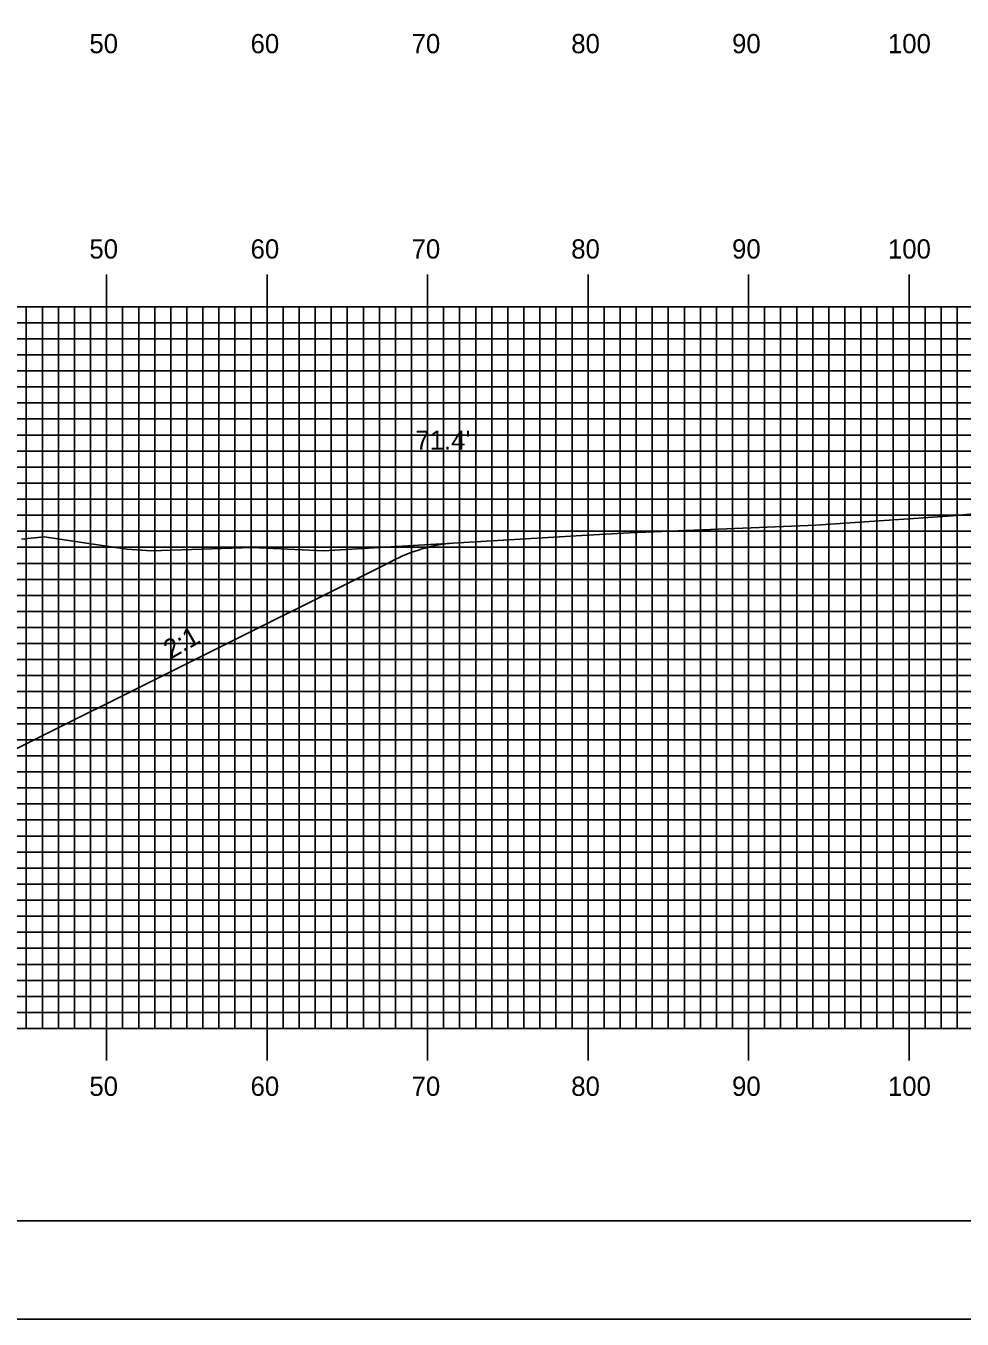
# Model space of a CAD drawing. Extents: x 1794453 to 1794796, y 442591 to 442811.
# Drawn here: x 1794663.3 to 1794721.6, y 442590.5 to 442671.2 of the extents above; entities that cross this region are included whole.
import ezdxf

# ---------------------------------------------------------------- set-up
doc = ezdxf.new("R2010")
doc.units = 0
for name, color, linetype in [('ANNOTATION', 7, 'Continuous'), ('BORDER', 7, 'Continuous'), ('D_Roadway_Centerline', 7, 'Continuous'), ('D_Roadway_SlopeLines', 7, 'Continuous'), ('D_Text_Standard', 7, 'Continuous'), ('H_V ANNOTATION', 7, 'Continuous'), ('MAJOR', 7, 'Continuous'), ('MINOR', 7, 'Continuous'), ('PLOT BOUNDARY', 7, 'Continuous'), ('S_Roadway_Centerline', 7, 'Continuous')]:
    doc.layers.add(name, color=color, linetype=linetype)

msp = doc.modelspace()

# ---------------------------------------------------------------- linework, layer by layer
at = {"layer": 'BORDER'}
msp.add_lwpolyline([(1794468.74, 442596.665), (1794788.74, 442596.665), (1794788.74, 442806.665), (1794468.74, 442806.665)], close=True, dxfattribs=at)
at = {"layer": 'D_Roadway_Centerline'}
msp.add_arc((1794690.818, 442628.973), 10, 96.45569, 116.56505, dxfattribs=at)
at = {"layer": 'D_Roadway_SlopeLines'}
for p, q in [((1794661.442, 442625.465), (1794685.8, 442637.644)), ((1794685.8, 442637.644), (1794686.346, 442637.917))]:
    msp.add_line(p, q, dxfattribs=at)
at = {"layer": 'MAJOR'}
for p, q in [((1794668.34, 442655.669), (1794668.34, 442653.665)), ((1794678.34, 442655.669), (1794678.34, 442653.665)), ((1794688.34, 442655.669), (1794688.34, 442653.665)), ((1794698.34, 442655.669), (1794698.34, 442653.665)), ((1794708.34, 442655.669), (1794708.34, 442653.665)), ((1794718.34, 442655.669), (1794718.34, 442653.665)), ((1794478.34, 442653.665), (1794758.34, 442653.665)), ((1794478.34, 442653.665), (1794758.34, 442653.665)), ((1794668.34, 442608.665), (1794668.34, 442653.665)), ((1794678.34, 442608.665), (1794678.34, 442653.665)), ((1794688.34, 442608.665), (1794688.34, 442653.665)), ((1794698.34, 442608.665), (1794698.34, 442653.665)), ((1794708.34, 442608.665), (1794708.34, 442653.665)), ((1794718.34, 442608.665), (1794718.34, 442653.665)), ((1794478.34, 442648.665), (1794758.34, 442648.665)), ((1794478.34, 442643.665), (1794758.34, 442643.665)), ((1794478.34, 442638.665), (1794758.34, 442638.665)), ((1794478.34, 442633.665), (1794758.34, 442633.665)), ((1794478.34, 442628.665), (1794758.34, 442628.665)), ((1794478.34, 442623.665), (1794758.34, 442623.665)), ((1794478.34, 442618.665), (1794758.34, 442618.665)), ((1794478.34, 442613.665), (1794758.34, 442613.665)), ((1794478.34, 442608.665), (1794758.34, 442608.665)), ((1794478.34, 442608.665), (1794758.34, 442608.665)), ((1794668.34, 442606.661), (1794668.34, 442608.665)), ((1794678.34, 442606.661), (1794678.34, 442608.665)), ((1794688.34, 442606.661), (1794688.34, 442608.665)), ((1794698.34, 442606.661), (1794698.34, 442608.665)), ((1794708.34, 442606.661), (1794708.34, 442608.665)), ((1794718.34, 442606.661), (1794718.34, 442608.665))]:
    msp.add_line(p, q, dxfattribs=at)
at = {"layer": 'MINOR'}
for p, q in [((1794663.34, 442608.665), (1794663.34, 442653.665)), ((1794664.34, 442608.665), (1794664.34, 442653.665)), ((1794665.34, 442608.665), (1794665.34, 442653.665)), ((1794666.34, 442608.665), (1794666.34, 442653.665)), ((1794667.34, 442608.665), (1794667.34, 442653.665)), ((1794669.34, 442608.665), (1794669.34, 442653.665)), ((1794670.34, 442608.665), (1794670.34, 442653.665)), ((1794671.34, 442608.665), (1794671.34, 442653.665)), ((1794672.34, 442608.665), (1794672.34, 442653.665)), ((1794673.34, 442608.665), (1794673.34, 442653.665)), ((1794674.34, 442608.665), (1794674.34, 442653.665)), ((1794675.34, 442608.665), (1794675.34, 442653.665)), ((1794676.34, 442608.665), (1794676.34, 442653.665)), ((1794677.34, 442608.665), (1794677.34, 442653.665)), ((1794679.34, 442608.665), (1794679.34, 442653.665)), ((1794680.34, 442608.665), (1794680.34, 442653.665)), ((1794681.34, 442608.665), (1794681.34, 442653.665)), ((1794682.34, 442608.665), (1794682.34, 442653.665)), ((1794683.34, 442608.665), (1794683.34, 442653.665)), ((1794684.34, 442608.665), (1794684.34, 442653.665)), ((1794685.34, 442608.665), (1794685.34, 442653.665)), ((1794686.34, 442608.665), (1794686.34, 442653.665)), ((1794687.34, 442608.665), (1794687.34, 442653.665)), ((1794689.34, 442608.665), (1794689.34, 442653.665)), ((1794690.34, 442608.665), (1794690.34, 442653.665)), ((1794691.34, 442608.665), (1794691.34, 442653.665)), ((1794692.34, 442608.665), (1794692.34, 442653.665)), ((1794693.34, 442608.665), (1794693.34, 442653.665)), ((1794694.34, 442608.665), (1794694.34, 442653.665)), ((1794695.34, 442608.665), (1794695.34, 442653.665)), ((1794696.34, 442608.665), (1794696.34, 442653.665)), ((1794697.34, 442608.665), (1794697.34, 442653.665)), ((1794699.34, 442608.665), (1794699.34, 442653.665)), ((1794700.34, 442608.665), (1794700.34, 442653.665)), ((1794701.34, 442608.665), (1794701.34, 442653.665)), ((1794702.34, 442608.665), (1794702.34, 442653.665)), ((1794703.34, 442608.665), (1794703.34, 442653.665)), ((1794704.34, 442608.665), (1794704.34, 442653.665)), ((1794705.34, 442608.665), (1794705.34, 442653.665)), ((1794706.34, 442608.665), (1794706.34, 442653.665)), ((1794707.34, 442608.665), (1794707.34, 442653.665)), ((1794709.34, 442608.665), (1794709.34, 442653.665)), ((1794710.34, 442608.665), (1794710.34, 442653.665)), ((1794711.34, 442608.665), (1794711.34, 442653.665)), ((1794712.34, 442608.665), (1794712.34, 442653.665)), ((1794713.34, 442608.665), (1794713.34, 442653.665)), ((1794714.34, 442608.665), (1794714.34, 442653.665)), ((1794715.34, 442608.665), (1794715.34, 442653.665)), ((1794716.34, 442608.665), (1794716.34, 442653.665)), ((1794717.34, 442608.665), (1794717.34, 442653.665)), ((1794719.34, 442608.665), (1794719.34, 442653.665)), ((1794720.34, 442608.665), (1794720.34, 442653.665)), ((1794721.34, 442608.665), (1794721.34, 442653.665)), ((1794478.34, 442652.665), (1794758.34, 442652.665)), ((1794478.34, 442651.665), (1794758.34, 442651.665)), ((1794478.34, 442650.665), (1794758.34, 442650.665)), ((1794478.34, 442649.665), (1794758.34, 442649.665)), ((1794478.34, 442647.665), (1794758.34, 442647.665)), ((1794478.34, 442646.665), (1794758.34, 442646.665)), ((1794478.34, 442645.665), (1794758.34, 442645.665)), ((1794478.34, 442644.665), (1794758.34, 442644.665)), ((1794478.34, 442642.665), (1794758.34, 442642.665)), ((1794478.34, 442641.665), (1794758.34, 442641.665)), ((1794478.34, 442640.665), (1794758.34, 442640.665)), ((1794478.34, 442639.665), (1794758.34, 442639.665)), ((1794478.34, 442637.665), (1794758.34, 442637.665)), ((1794478.34, 442636.665), (1794758.34, 442636.665)), ((1794478.34, 442635.665), (1794758.34, 442635.665)), ((1794478.34, 442634.665), (1794758.34, 442634.665)), ((1794478.34, 442632.665), (1794758.34, 442632.665)), ((1794478.34, 442631.665), (1794758.34, 442631.665)), ((1794478.34, 442630.665), (1794758.34, 442630.665)), ((1794478.34, 442629.665), (1794758.34, 442629.665)), ((1794478.34, 442627.665), (1794758.34, 442627.665)), ((1794478.34, 442626.665), (1794758.34, 442626.665)), ((1794478.34, 442625.665), (1794758.34, 442625.665)), ((1794478.34, 442624.665), (1794758.34, 442624.665)), ((1794478.34, 442622.665), (1794758.34, 442622.665)), ((1794478.34, 442621.665), (1794758.34, 442621.665)), ((1794478.34, 442620.665), (1794758.34, 442620.665)), ((1794478.34, 442619.665), (1794758.34, 442619.665)), ((1794478.34, 442617.665), (1794758.34, 442617.665)), ((1794478.34, 442616.665), (1794758.34, 442616.665)), ((1794478.34, 442615.665), (1794758.34, 442615.665)), ((1794478.34, 442614.665), (1794758.34, 442614.665)), ((1794478.34, 442612.665), (1794758.34, 442612.665)), ((1794478.34, 442611.665), (1794758.34, 442611.665)), ((1794478.34, 442610.665), (1794758.34, 442610.665)), ((1794478.34, 442609.665), (1794758.34, 442609.665))]:
    msp.add_line(p, q, dxfattribs=at)
at = {"layer": 'PLOT BOUNDARY'}
msp.add_lwpolyline([(1794452.553, 442590.547), (1794792.553, 442590.547), (1794792.553, 442810.547), (1794452.553, 442810.547)], close=True, dxfattribs=at)
at = {"layer": 'S_Roadway_Centerline'}
msp.add_lwpolyline([(1794663.047, 442639.173), (1794664.443, 442639.315), (1794669.598, 442638.545), (1794671.135, 442638.442), (1794677.411, 442638.642), (1794681.849, 442638.451), (1794698.305, 442639.412), (1794700.928, 442639.577), (1794712.523, 442640.051), (1794721.041, 442640.627), (1794736.343, 442642.062), (1794738.863, 442642.231), (1794748.21, 442643.105), (1794757.223, 442643.674), (1794758.34, 442643.741)], dxfattribs=at)

# ---------------------------------------------------------------- texts
at = {"layer": 'ANNOTATION'}
msp.add_text('2:1', height=1.2, rotation=29.74493, dxfattribs=at).set_placement((1794672.332, 442631.664))
msp.add_text('2:1', height=1.2, rotation=29.74493, dxfattribs=at).set_placement((1794672.332, 442631.664))
at = {"layer": 'D_Text_Standard'}
msp.add_text("71.4'", height=1.2, dxfattribs=at).set_placement((1794687.58, 442644.742))
at = {"layer": 'H_V ANNOTATION'}
for s, p in [('50', (1794667.269, 442669.465)), ('60', (1794677.312, 442669.465)), ('70', (1794687.344, 442669.465)), ('80', (1794697.291, 442669.465)), ('90', (1794707.312, 442669.465)), ('100', (1794717.023, 442669.465)), ('50', (1794667.269, 442656.665)), ('60', (1794677.312, 442656.665)), ('70', (1794687.344, 442656.665)), ('80', (1794697.291, 442656.665)), ('90', (1794707.312, 442656.665)), ('100', (1794717.023, 442656.665)), ('50', (1794667.269, 442604.465)), ('60', (1794677.312, 442604.465)), ('70', (1794687.344, 442604.465)), ('80', (1794697.291, 442604.465)), ('90', (1794707.312, 442604.465)), ('100', (1794717.023, 442604.465))]:
    msp.add_text(s, height=1.2, dxfattribs=at).set_placement(p)

doc.saveas('drawing.dxf')
